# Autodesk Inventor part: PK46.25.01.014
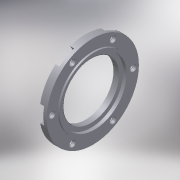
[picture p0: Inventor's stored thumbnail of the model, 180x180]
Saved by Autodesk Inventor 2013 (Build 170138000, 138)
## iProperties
Created: 2005-04
Part Number: PK46.25.01.014
Material: Steel, Mild
Document SubType Name: Modeling
Designer: salex
Manufacturer: Standard
Standards Organization: Custom
Density: 7.86 g/cm^3
Author: salex
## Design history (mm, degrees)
sketch "Эскиз1"
  geometry: L1 (0, 0)-(97.878, 0); L2 (0, 82.5)-(0, 50); L3 (0, 50)-(10, 50); L4 (10, 50)-(10, 57.5); L5 (10, 57.5)-(16, 57.5); L6 (16, 57.5)-(16, 62.5); L7 (16, 62.5)-(13, 62.5); L8 (13, 62.5)-(13, 82.5); L9 (13, 82.5)-(0, 82.5)
  constraints: 18 end point, 6 parallel, 2 perpendicular, 1 horizontal, 1 other
  dimensions: "d0" = 0 distance from line of L1.start L2; "d1" = 165 diameter of L9 L1; "d2" = 100 diameter of L3 L1; "d3" = 115 diameter of L5 L1; "d4" = 125 diameter of L7 L1; "d5" = 3 distance of L6.end L7.end; "d6" = 16 distance between parallel lines of L6 L2; "d7" = 6 distance between parallel lines of L6 L4
revolve "Вращение1" sketch "Эскиз1" stored, may be unused: angle "d8" = 90 deg
sketch "Эскиз2"
  geometry: C1 r 82.5 at (0, 0) reference; C2 r 5.5 at (0, 72.5)
  constraints: 1 centre point
  dimensions: "d9" = 11 diameter of C2; "d10" = 0 horizontal distance of C1.centre C2.centre; "d11" = 72.5 distance of C1.centre C2.centre
extrude "Выдавливание1" cut sketch "Эскиз2" stored distance "d12" = 10; taper "d13" = 0 deg
sketch "Эскиз3"
  geometry: L1 (0, 0)-(0, 72.5); L2 (15, 72.5)-(15, 81.125); L3 (-15, 72.5)-(-15, 81.125); C1 r 5.5 at (0, 72.5) reference; C2 r 50 at (0, 0) reference; A1 r 15 centre (0, 72.5) between (-15, 72.5) and (15, 72.5); A2 r 82.5 centre (0, 0) between (-15, 81.125) and (15, 81.125) reference
  constraints: 6 end point, 4 point on circle, 2 parallel, 2 tangent, 1 centre point, 1 coincident, 1 vertical
  dimensions: "d17" = 30 diameter of A1
extrude "Выдавливание2" cut sketch "Эскиз3" distance "d18" = 7; taper "d19" = 0 deg
pattern_circular "Круговой массив1" dims angle "d16" = 360 deg
body "Solid1"
